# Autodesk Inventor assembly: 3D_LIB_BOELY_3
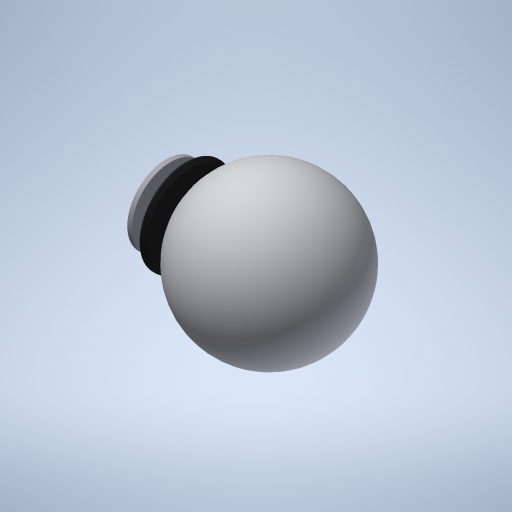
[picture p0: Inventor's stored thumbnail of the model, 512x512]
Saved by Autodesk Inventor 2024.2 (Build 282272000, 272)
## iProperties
Created: 2024-05
Part Number: 3D_LIB_BOELY_3
Project: 452 - BOELY
Description: BOELY Mirror - Assy
Document SubType Name: Assembly
Designer: Manuel
Manager: Filip
Company: DARK
Author: Manuel
Revision Number: v0
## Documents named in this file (8)
- C:\Users\Stage\Desktop\Stage Karsten\armatures\452 - BOELY\452_KARSTEN\3D_LIB_BOELY_3.iam
- N:\LIBRARY\FITTINGEN\BJB 25.834_G9.ipt
- N:\LIBRARY\FITTINGEN\BJB 25.934_for G9.ipt
- C:\Users\Stage\Desktop\Stage Karsten\armatures\452 - BOELY\Glass Sphere Dia.100mm.ipt
- N:\LIBRARY\LAMPEN\LED\G9-6W-2700K-CRI 90.ipt
- C:\Users\Stage\Desktop\Stage Karsten\armatures\452 - BOELY\452-003.ipt
- N:\LIBRARY\BEVESTIGING\Draadstang-trompetnipple\Draadstang M10x1 L25.ipt
- C:\Users\Stage\Desktop\Stage Karsten\armatures\452 - BOELY\452-004.ipt
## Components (7 placed, 7 different names)
1. BJB 25.834_G9:1 — Mate:5, Mate:6, Angle:3, Mate:14, Mate:15, Mate:17
2. BJB 25.934_for G9:1 — Angle:1, Mate:3, Mate:4, Mate:5, Mate:6, Mate:17, Mate:18, Mate:19, Angle:4, Mate:20
3. Draadstang M10x1 L25:1 — Angle:1, Mate:3, Mate:4, Mate:22
4. Glass Sphere Dia.100mm:1 — Angle:4, Mate:20
5. G9-6W-2700K-CRI 90:1 — Angle:3, Mate:14, Mate:15
6. 452-003:1 — Flush:1, Flush:2, Flush:3, Mate:18, Mate:19, Mate:21
7. 452-004:1 — Mate:21, Mate:22
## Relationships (18: Mate 12, Angle 3, Flush 3)
- Angle:1: BJB 25.934_for G9:1 ↔ Draadstang M10x1 L25:1
- Mate:3: BJB 25.934_for G9:1 ↔ Draadstang M10x1 L25:1
- Mate:4: BJB 25.934_for G9:1 ↔ Draadstang M10x1 L25:1
- Mate:5: BJB 25.834_G9:1 ↔ BJB 25.934_for G9:1
- Mate:6: BJB 25.834_G9:1 ↔ BJB 25.934_for G9:1
- Angle:3: BJB 25.834_G9:1 ↔ G9-6W-2700K-CRI 90:1
- Mate:14: BJB 25.834_G9:1 ↔ G9-6W-2700K-CRI 90:1
- Mate:15: BJB 25.834_G9:1 ↔ G9-6W-2700K-CRI 90:1
- Mate:17: BJB 25.834_G9:1 ↔ BJB 25.934_for G9:1
- Flush:1: 452-003:1
- Flush:2: 452-003:1
- Flush:3: 452-003:1
- Mate:18: BJB 25.934_for G9:1 ↔ 452-003:1
- Mate:19: BJB 25.934_for G9:1 ↔ 452-003:1
- Angle:4: BJB 25.934_for G9:1 ↔ Glass Sphere Dia.100mm:1
- Mate:20: BJB 25.934_for G9:1 ↔ Glass Sphere Dia.100mm:1
- Mate:21: 452-003:1 ↔ 452-004:1
- Mate:22: Draadstang M10x1 L25:1 ↔ 452-004:1
